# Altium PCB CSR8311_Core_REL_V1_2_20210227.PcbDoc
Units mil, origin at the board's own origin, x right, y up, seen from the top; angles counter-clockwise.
Board outline 1105 x 1105 mil, 2 copper layers (Top Layer, Bottom Layer), stack 50.044 mil thick; 31 components, 38 nets, 155 pads, 42 vias.
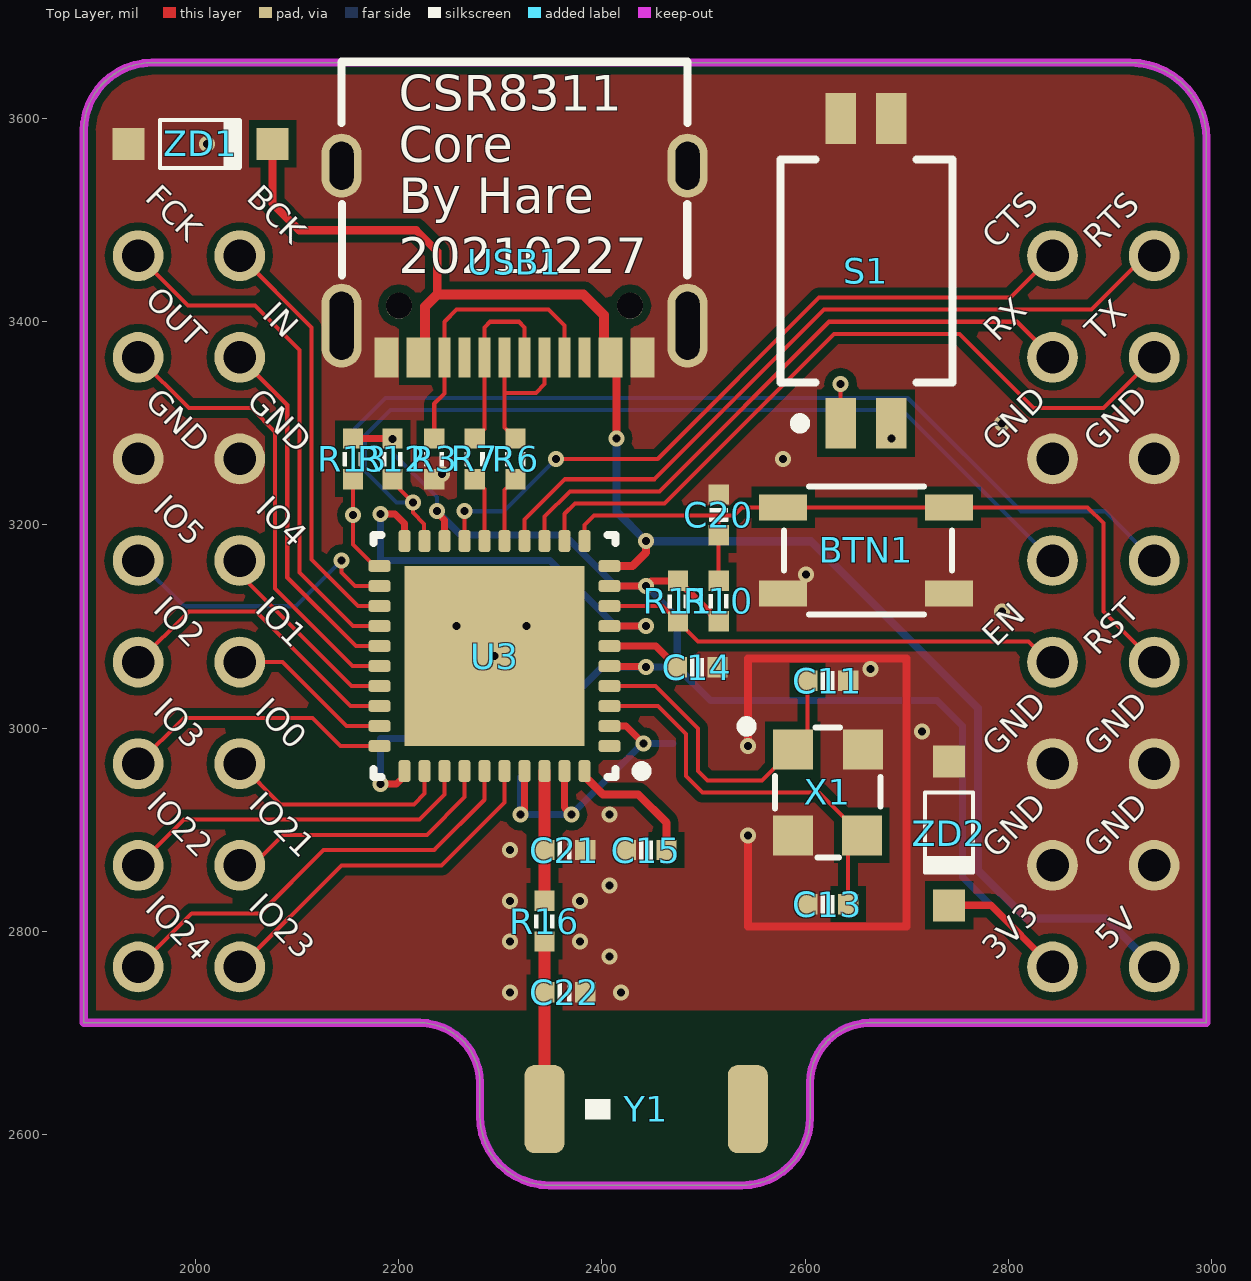
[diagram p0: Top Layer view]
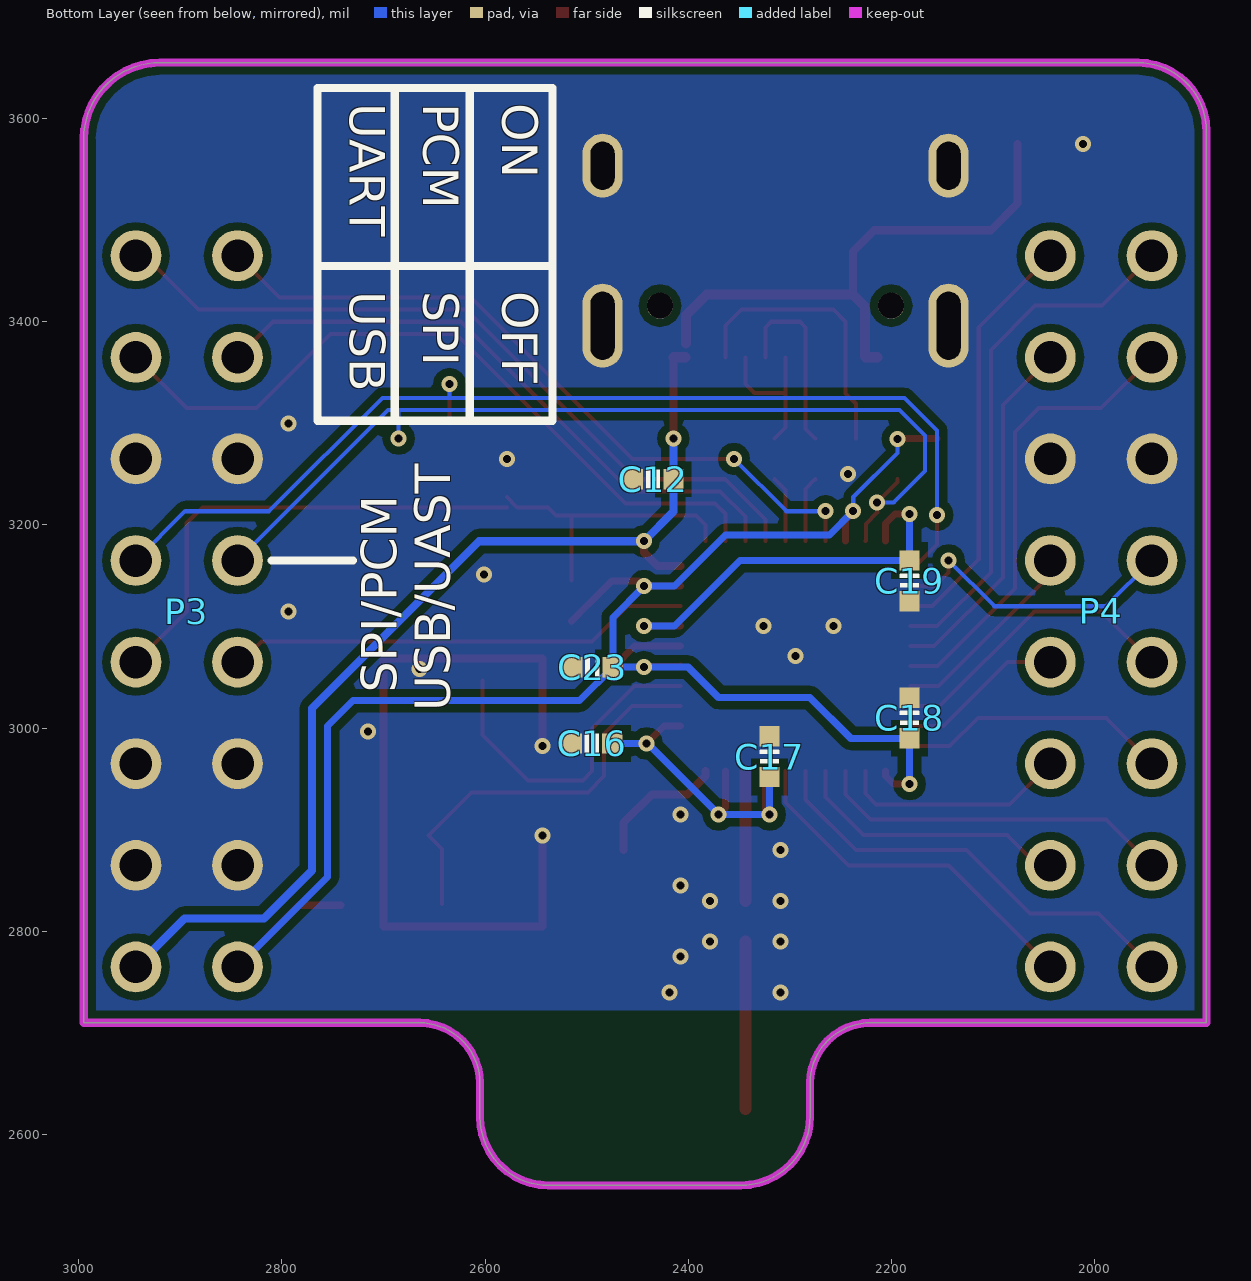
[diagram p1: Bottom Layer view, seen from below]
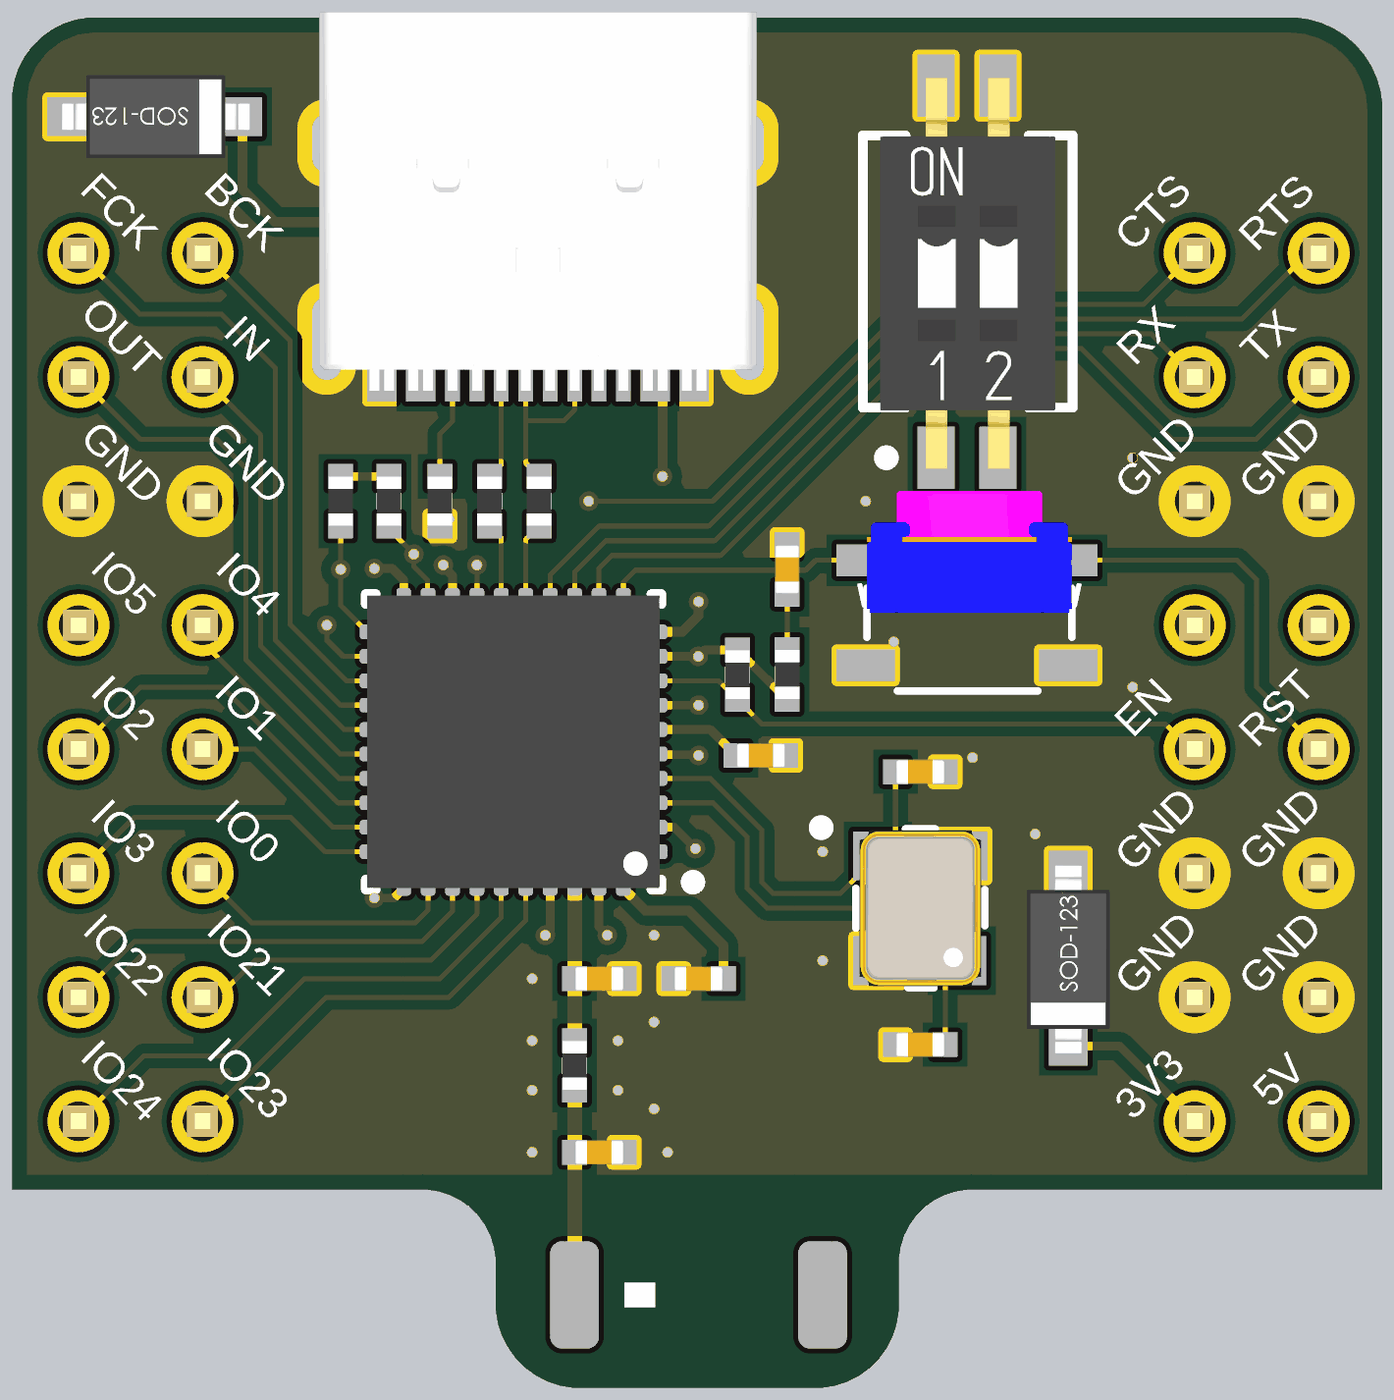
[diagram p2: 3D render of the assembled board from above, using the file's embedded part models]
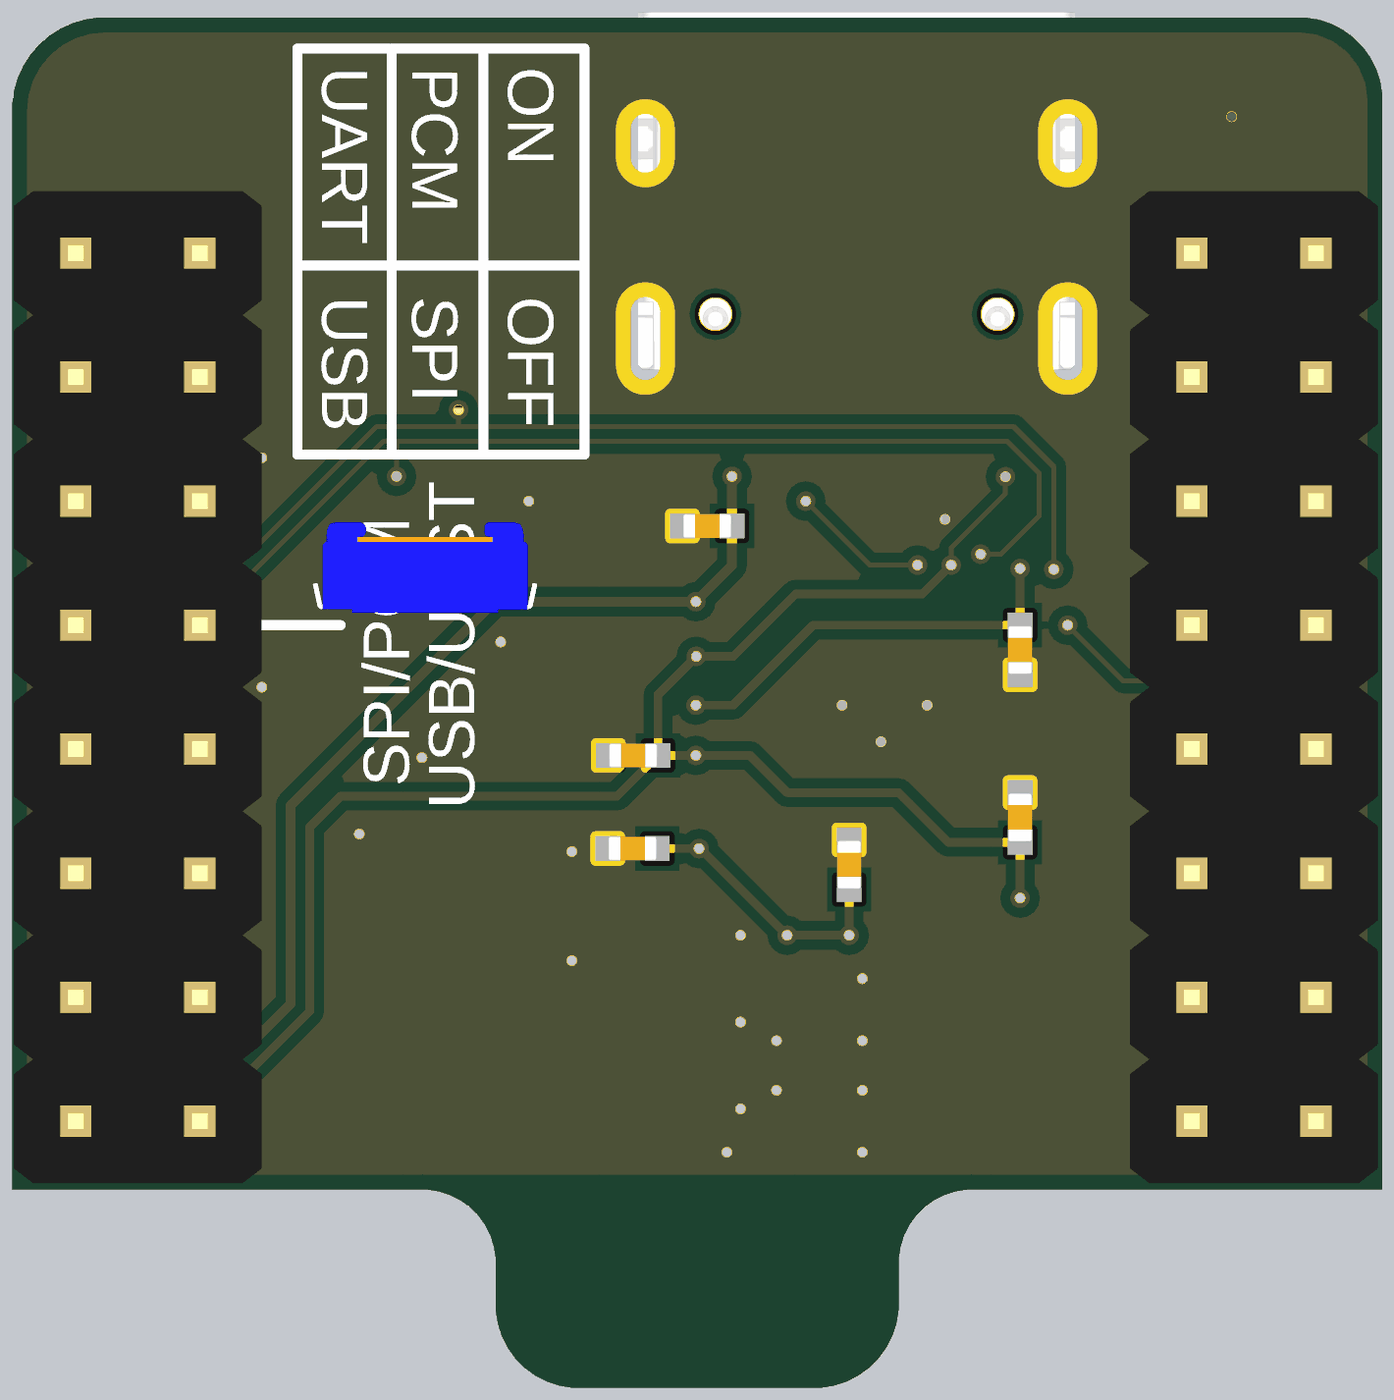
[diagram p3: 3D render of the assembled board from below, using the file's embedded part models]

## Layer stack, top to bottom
Top Solder: solder mask 0.4, Solder Resist, Dk 3.5
Top Layer: signal copper 1.4
Dielectric 1: dielectric 47.2441, FR-4, Dk 4.8
Bottom Layer: signal copper 1.4
Bottom Solder: solder mask 0.4, Solder Resist, Dk 3.5

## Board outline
2220.5,2710 cw(c2220.5,2650.51) 2280,2650.51 2280,2618.28 ccw(c2348.28,2618.28) 2348.28,2550 2537.61,2550 ccw(c2537.61,2617.39) 2605,2617.39 2605,2650.5 cw(c2664.5,2650.5) 2664.5,2710 2995,2710 2995,3580 ccw(c2920,3580) 2920,3655 1957.39,3655 ccw(c1957.39,3587.61) 1890,3587.61 1890,2710

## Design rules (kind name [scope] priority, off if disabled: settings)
Clearance [All] p1: gap=7.87 ignorepadtopadclearanceinfootprint=TRUE
ComponentClearance [All] p1: gap=0 collisioncheckmode=3 verticalgap=0 showdistances=FALSE
DiffPairsRouting [All] p1: maxlimit=10 minlimit=10 mostfreqgap=10 toplayer_minwidth=7.87 toplayer_maxwidth=15 toplayer_prefwidth=7.87 bottomlayer_minwidth=7.87 bottomlayer_maxwidth=15 bottomlayer_prefwidth=7.87 maxuncoupledlength=500
MatchedLengths SD_CARD_MatchedLengths [InNetClass('SD_CARD')] p1: tolerance=400 checknetsindiffpair=FALSE checkdiffpairvsdiffpair=TRUE checkxsignals=TRUE checkothers=TRUE
PolygonConnect PolygonConnect_wifi [HasFootprint('RTL8723DU_MOUDLE')] p1: connectstyle=Relief reliefconductorwidth=10 reliefentries=4 polygonreliefangle="90 Angle" airgapwidth=10
PolygonConnect PolygonConnect_Res [HasFootprint('RES_0603')] p2: connectstyle=Relief reliefconductorwidth=10 reliefentries=4 polygonreliefangle="90 Angle" airgapwidth=10
PolygonConnect PolygonConnect_Core [HasFootprint('CORE-82PIN-SMD')] p3: connectstyle=Relief reliefconductorwidth=10 reliefentries=4 polygonreliefangle="90 Angle" airgapwidth=10
PolygonConnect [All] p4: connectstyle=Direct reliefconductorwidth=10 reliefentries=4 polygonreliefangle="90 Angle" airgapwidth=10
RoutingVias [All] p1: holewidth=28 width=50 viastyle="Through Hole" minholewidth=7.87 minwidth=15.75 maxholewidth=28 maxwidth=50
SolderMaskExpansion [All] p1: expansion=4
Width Width_PWR [InNetClass('PWR')] p1: maxlimit=23.62 minlimit=7.87 preferedwidth=10
Width [All] p2: maxlimit=23.62 minlimit=4 preferedwidth=8
28 further rules are at their usual default settings.

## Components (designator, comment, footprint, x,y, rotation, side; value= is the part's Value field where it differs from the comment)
BTN1 "Button" BTN-4P-4.2*3.4*2.5 2660,3175 r180 top
C11 "10pF" CAP_0402 2622.41,3046.76 r180 top
C12 "2.2uF" CAP_0402 2434.45,3245 r0 bottom
C13 "10pF" CAP_0402 2622.41,2826.76 r0 top
C14 "2.2uF" CAP_0402 2493.85,3060 r180 top
C15 "470nF" CAP_0402 2443.59,2880 r180 top
C16 "15pF" CAP_0402 2494.69,2984.98 r0 bottom
C17 "2.2uF" CAP_0402 2320,2971.88 r90 bottom
C18 "0.1uF" CAP_0402 2182.17,3010 r270 bottom
C19 "2.2uF" CAP_0402 2182.17,3145 r270 bottom
C20 "0.1uF" CAP_0402 2515,3210 r90 top
C21 "NC" CAP_0402 2363.59,2880 r180 top locked
C22 "NC" CAP_0402 2363.59,2740 r180 top locked
C23 "2.2uF" CAP_0402 2494.17,3060 r0 bottom
P3 "DIP 2x8" HDR2X8_2.54_180 2943.59,3465 r180 bottom locked
P4 "DIP 2x8" HDR2X8_2.54_180 2043.59,3465 r180 bottom locked
R3 "5.1K" RES_0402 2235,3265 r90 top
R6 "22R" RES_0402 2315,3265 r90 top
R7 "22R" RES_0402 2275,3265 r90 top
R10 "10K" RES_0402 2515,3125.19 r90 top
R11 "10K" RES_0402 2475,3125 r270 top
R12 "10K" RES_0402 2193.98,3265 r270 top
R13 "10K" RES_0402 2155,3265 r270 top
R16 "0R" RES_0402 2343.59,2810 r270 top locked
S1 "SW-2P" SW-SMD-2-1.27 2660.59,3448.63 r90 top
U3 "CSR8311A08" QFN-40-P0.5 2295.37,3071.98 r90 top locked
USB1 "Type-C" USB-Type-C 2314.06,3459.29 r90 top locked
X1 "M26000J134" XTAL_3225-4 2622.41,2936.76 r270 top
Y1 "AN2051-245" ANT_2.4G_5.1X2.0 2443.59,2625 r0 top locked
ZD1 "BZT52C5V1S" SOD-123 2005,3575 r180 top
ZD2 "BZT52C3V9S" SOD-123 2741.69,2896.5 r90 top

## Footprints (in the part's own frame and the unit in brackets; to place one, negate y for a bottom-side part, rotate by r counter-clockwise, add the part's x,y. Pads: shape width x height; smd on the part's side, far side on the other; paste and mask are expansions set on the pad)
ANT_2.4G_5.1X2.0 [mm]
  rrect50% 1x2.2 smd: 1(-2.54,0) 2(2.54,0)
  silkscreen extent -1.52,-0.25 -0.89,0.25
BTN-4P-4.2*3.4*2.5 [mm] "SKRPABE010"
  rect 1.2x0.65 smd: 1(-2.075,1.075) 1(2.075,1.075) 2(-2.075,-1.075) 2(2.075,-1.075)
  silkscreen extent -2.15,-1.6 2.05,1.6, body extent -2.35,-1.6 2.25,1.6, height 2.5
CAP_0402 [mil]
  rect 20x20 smd: 1(-20,0) 2(20,0)
  silkscreen extent -7,-9 7,9, body extent -20,-10 20,10, height 20
HDR2X8_2.54_180 [mil]
  round 50 hole 32: 1(0,0) 2(100,0) 3(0,-100) 4(100,-100) 5(0,-200) 6(100,-200) 7(0,-300) 8(100,-300) 9(0,-400) 10(100,-400) 11(0,-500) 12(100,-500) 13(0,-600) 14(100,-600) 15(0,-700) 16(100,-700)
  body extent -50,-750 150,50, height 335
QFN-40-P0.5 [mm] "PQFN, 40-Leads, Body 5.98x5.98mm, Pitch 0.50mm, Thermal Pad 4.62x4.62mm, IPC Medium Density"
  rrect50% 0.3x0.55 smd: 1(-2.275,-2.851) 2(-1.775,-2.851) 3(-1.275,-2.851) 4(-0.775,-2.851) 5(-0.275,-2.851) 6(0.225,-2.851) 7(0.725,-2.851) 8(1.225,-2.851) 9(1.725,-2.851) 10(2.225,-2.851) 21(2.225,2.902) 22(1.725,2.902) 23(1.225,2.902) 24(0.725,2.902) 25(0.225,2.902) 26(-0.275,2.902) 27(-0.775,2.902) 28(-1.275,2.902) 29(-1.775,2.902) 30(-2.275,2.902)
  rrect50% 0.55x0.3 smd: 11(2.851,-2.225) 12(2.851,-1.725) 13(2.851,-1.225) 14(2.851,-0.725) 15(2.851,-0.225) 16(2.851,0.275) 17(2.851,0.775) 18(2.851,1.275) 19(2.851,1.775) 20(2.851,2.275) 31(-2.902,2.275) 32(-2.902,1.775) 33(-2.902,1.275) 34(-2.902,0.775) 35(-2.902,0.275) 36(-2.902,-0.225) 37(-2.902,-0.725) 38(-2.902,-1.225) 39(-2.902,-1.725) 40(-2.902,-2.225)
  rect 4.5x4.5 smd: 41(-0.025,0.025)
  silkscreen extent -3.05,-3.77 3,3.05, body extent -3.03,-2.97 2.97,3.03, height 0.9
RES_0402 [mil]
  rect 20x20 smd: 1(-20,0) 2(20,0)
  silkscreen extent -7,-10 7,10, body extent -20,-10 20,10, height 14
SOD-123 [mm]
  rect 0.8x0.8 smd: 1(1.8,0) 2(-1.8,0)
  silkscreen extent -1.02,-0.6 1.02,0.6, body extent -1.95,-0.85 1.9,0.85, height 1.42
SW-SMD-2-1.27 [mm]
  rect 1.27x0.76 smd: 1(-3.775,0.65) 2(-3.775,-0.62) 3(3.845,-0.62) 4(3.845,0.65)
  silkscreen extent -3.9,-2.15 2.82,2.15, body extent -4,-1.79 4,1.79, height 2.1
USB-Type-C [mm]
  round 0.65 hole 0.65: 0(-1.105,2.89) 0(-1.105,-2.89)
  oval 1.6x1 hole 0.6 slot 1.2 at 0 deg: 1(2.395,4.325) 2(2.395,-4.325)
  oval 2.1x1 hole 0.6 slot 1.7 at 0 deg: 3(-1.605,-4.325) 4(-1.605,4.325)
  rect 1x0.3 smd: A1(-2.395,-3.35) A4(-2.395,-2.55) A5(-2.395,-1.25) A6(-2.395,-0.25) A7(-2.395,0.25) A8(-2.395,1.25) A9(-2.395,2.55) A12(-2.395,3.35) B1(-2.395,3.05) B4(-2.395,2.25) B5(-2.395,1.75) B6(-2.395,0.75) B7(-2.395,-0.75) B8(-2.395,-1.75) B9(-2.395,-2.25) B12(-2.395,-3.05)
  silkscreen extent -0.34,-4.33 4.99,4.33, body extent -2.67,-4.48 5.08,4.48, height 3.26
XTAL_3225-4 [mm]
  rect 1x1 smd: 1(-1.074,-0.874) 2(1.074,-0.874) 3(1.074,0.848) 4(-1.074,0.874)
  silkscreen extent -1.78,-2.16 1.63,1.32, body extent -1.6,-1.25 1.6,1.25, height 0.61

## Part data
C11 C12 C13 C14 C15 C16 C17 C18 C19 C20 C21 C22 C23: library part CAP, "Capacitor"
P3 P4: library part HDR2x8, "Header"
R3 R6 R7 R10 R11 R12 R13 R16: library part RES, "Resistor"
S1: "拨码开关2P"
U3: library part CSR8311, "Bluetooth v4.1 single-chip radio and baseband IC for automotive applications."
USB1: library part USB-Type-C
X1: library part XTAL-4P
Y1: library part ANTENNA
ZD1 ZD2: library part Diode-ZD, "Zender Diode"

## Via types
v1: diameter 15.75, hole 7.87, Top Layer to Bottom Layer, tented both sides, 42 vias

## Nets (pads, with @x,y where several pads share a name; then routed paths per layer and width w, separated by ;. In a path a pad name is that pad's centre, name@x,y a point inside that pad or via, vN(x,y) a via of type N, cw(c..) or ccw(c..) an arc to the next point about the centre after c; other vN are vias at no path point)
BT_NRST: BTN1.2 C20.1 P3.9 R10.2 U3.11 | length 765.8
  Top Layer w4: U3.11 2382.96,3199.91 2392.42,3209.38 2515,3209.38 ; R10.2 2515,3209.38 ; BTN1.2@2578.31,3217.32 2741.69,3217.32 2878.06,3217.32 2893.59,3201.79 2893.59,3115 P3.9 ; BTN1.2@2578.31,3227.32 2568.31,3217.32 2537.98,3217.32 2530.04,3209.38 2515,3209.38
BT_PCM2_CLK: P4.1 U3.23 | length 414.3
  Top Layer w4: P4.1 2114.08,3394.5 2114.08,3165.92 2159.81,3120.19 U3.23
BT_PCM2_IN: P4.3 U3.25 | length 354.8
  Top Layer w4: P4.3 2090.33,3318.25 2090.33,3148.38 2157.89,3080.82 U3.25
BT_PCM2_OUT: P4.4 U3.26 | length 453.7
  Top Layer w4: P4.4 1993.59,3315 2055,3315 2078.46,3291.54 2078.46,3137.33 2154.65,3061.13 U3.26
BT_PCM2_SYNC: P4.2 U3.24 | length 516.8
  Top Layer w4: P4.2 1992.8,3415.79 2058.77,3415.79 2102.21,3372.35 2102.21,3153.3 2155,3100.5 U3.24
BT_PIO0: P4.11 U3.32 | length 225
  Top Layer w4: P4.11 2083.59,2925 2215,2925 2225.48,2935.48 U3.32
BT_PIO1: P4.9 U3.29 | length 163.6
  Top Layer w4: P4.9 2085.85,3065 2148.77,3002.08 U3.29
BT_PIO2: P4.10 U3.28 | length 296.9
  Top Layer w4: P4.10 1993.59,3115 2059.4,3115 2152.64,3021.76 U3.28
BT_PIO3: P4.12 U3.30 | length 267.6
  Top Layer w4: P4.12 1988.59,3010 2115,3010 2142.61,2982.39 U3.30
BT_PIO4: P4.7 U3.27 | length 196.7
  Top Layer w4: P4.7 2045.08,3163.5 2045.08,3149.92 2153.55,3041.45 U3.27
BT_PIO5: P4.8 U3.22 | length 292.2
  Top Layer w4: v1(2143.78,3165) 2143.78,3153.01 2156.92,3139.87 U3.22
  Bottom Layer w4: P4.8 1988.59,3120 2098.78,3120 v1(2143.78,3165)
BT_PIO21: P4.13 U3.34 | length 274.7
  Top Layer w4: P4.13 2056.03,2865 2086.03,2895 2227.72,2895 2264.85,2932.12 U3.34
BT_PIO22: P4.14 U3.33 | length 353.5
  Top Layer w4: P4.14 1988.59,2910 2220.46,2910 2245.16,2934.7 U3.33
BT_PIO23: P4.15 U3.36 | length 358.5
  Top Layer w4: P4.15 2143.59,2865 2242.27,2865 2304.22,2926.95 U3.36
BT_PIO24: P4.16 U3.35 | length 437.3
  Top Layer w4: P4.16 1996.31,2817.72 2063.76,2817.72 2126.03,2880 2235,2880 2284.53,2929.53 U3.35
BT_RF: C21.2 R16.1 U3.38 | length 127.7
  Top Layer w11.81: R16.1 C21.2 U3.38
BT_SPI_PCM: P3.7 R13.2 S1.1 U3.21 | length 1102.3
  Top Layer w4: R13.2 v1(2155,3210) 2155,3180.76 2176.2,3159.56 U3.21 ; S1.1 v1(2635,3338.59)
  Bottom Layer w4: v1(2155,3210) 2155,3292.75 2187.25,3325 2635,3325 ; v1(2635,3338.59) 2635,3325 ; P3.7 2895.08,3213.5 2812.56,3213.5 2701.06,3325 2635,3325
BT_UART_CTS: P3.2 U3.17 | length 712.2
  Top Layer w4: U3.17 v1(2264.85,3213.5) ; v1(2355,3265) 2455,3265 2613.75,3423.75 2802.33,3423.75 P3.2
  Bottom Layer w4: v1(2264.85,3213.5) 2303.5,3213.5 v1(2355,3265)
BT_UART_RTS: P3.1 U3.14 | length 748.3
  Top Layer w4: U3.14 2323.9,3205.23 2363.67,3245 2451.79,3245 2618.67,3411.87 2881.87,3411.87 2935,3465 P3.1
BT_UART_RX: P3.4 U3.13 | length 617.9
  Top Layer w4: U3.13 2343.59,3208.13 2368.59,3233.13 2456.71,3233.13 2623.58,3400 2808.59,3400 P3.4
BT_UART_TX: P3.3 U3.12 | length 731.5
  Top Layer w4: U3.12 2363.27,3211.02 2373.5,3221.25 2461.63,3221.25 2628.5,3388.13 2751.87,3388.13 2825,3315 2893.59,3315 P3.3
BT_USB_D_N: R6.1 U3.15 | length 65.2
  Top Layer w4: U3.15 2304.22,3234.22 R6.1
BT_USB_D_P: R7.1 U3.16 | length 64.7
  Top Layer w4: R7.1 2284.53,3235.47 U3.16
BT_USB_UART: P3.8 R12.2 S1.2 U3.19 | length 945.1
  Top Layer w4: R12.2 2193.98,3242.32 v1(2213.98,3222.27) v1(2213.98,3222.27) 2213.98,3212.15 2225.07,3201.06 2225.07,3184.63 U3.19
  Bottom Layer w4: v1(2213.98,3222.27) 2197.73,3222.27 2166.87,3253.13 2166.87,3287.83 2192.17,3313.13 2685,3313.13 ; v1(2685,3285) 2685,3313.13 ; P3.8 2695.46,3313.13 2685,3313.13
BT_VREG_EN: P3.10 R11.2 U3.8 | length 458.8
  Top Layer w4: U3.8 2459.81,3120.19 R11.2 2494.69,3085.31 2820.06,3085.31 2840.38,3065 P3.10
GND: BTN1.1 C11.1 C12.2 C13.1 C14.1 C15.2 C16.2 C17.2 C18.1 C19.2 C20.2 C21.1 C22.1 C23.2 P3.5 P3.6 P3.11 P3.12 P3.13 P3.14 P4.5 P4.6 R3.1 S1.3 S1.4 U3.41 USB1.1 USB1.2 USB1.3 USB1.4 USB1.A1 USB1.A12 USB1.B1 USB1.B12 X1.2 X1.4 ZD1.1 ZD2.1 | length 752.2
  Top Layer w7.87: v1(2543.59,2894.49) 2543.59,2804.95 2700,2804.95 2700,3068.57 2543.59,3068.57 v1(2543.59,2982.39)
  other v1: 2309.37,2740 2418.59,2740 2407.63,2775 2309.37,2790 2378.59,2790 2309.37,2830 2378.59,2830 2407.63,2845 2309.37,2880 2407.63,2915 2715,2996.64 2664.5,3058.18 2294.37,3070.98 2257.13,3100.5 2325.71,3100.5 2793.59,3115 2601,3151.47 2242.75,3250.31 2578.31,3265 2793.59,3300 2011.56,3575
NetC14_2: C14.2 U3.6 | length 74.9
  Top Layer w7: U3.6 2453.03,3080.82 C14.2
NetC15_1: C15.1 U3.40 | length 131.5
  Top Layer w8: U3.40 2382.96,2952.8 2401.01,2934.75 2435.79,2934.75 2463.59,2906.95 C15.1
NetC16_1: C16.1 C17.1 U3.2 U3.37 U3.39 | length 346.3
  Top Layer w7: v1(2320,2915) 2323.9,2918.9 U3.37 ; U3.39 2363.27,2921.73 v1(2370,2915) ; U3.2 2423.9,3002.08 v1(2441.06,2984.89)
  Bottom Layer w7: C17.1 v1(2320,2915) v1(2370,2915) 2439.91,2984.91 v1(2441.06,2984.89) 2441.15,2984.98 C16.1@2469.98,2984.98
NetC19_1: C19.1 U3.7 U3.20 | length 414.4
  Top Layer w7: v1(2182.17,3210.68) 2196.54,3210.68 2205.79,3201.42 U3.20 ; U3.7 v1(2443.59,3100.5)
  Bottom Layer w7: v1(2182.17,3210.68) C19.1 2348.97,3165 2413.47,3100.5 v1(2443.59,3100.5)
NetC22_2: C22.2 R16.2 Y1.1 | length 165
  Top Layer w11.81: Y1.1 C22.2 R16.2
NetR3_2: R3.2 USB1.A5 USB1.B5 | length 279.9
  Top Layer w4: R3.2 2235,3319.29 2245.16,3329.45 USB1.B5 2245.16,3400 2257.03,3411.87 2347.5,3411.87 2363.27,3396.1 USB1.A5
USB_D_N: R6.2 USB1.A7 USB1.B7 | length 154
  Top Layer w4: USB1.A7 2304.22,3330.39 ; R6.2 2304.22,3295.78 2304.22,3330.39 ; USB1.B7 2343.59,3338.59 2335,3330 2304.61,3330 2304.22,3330.39
USB_D_P: R7.2 USB1.A6 USB1.B6 | length 186.9
  Top Layer w4: R7.2 2284.53,3294.53 USB1.B6 2284.53,3394.53 2290,3400 2318.43,3400 2323.9,3394.53 USB1.A6
VCC_3V3: C18.2 C23.1 P3.16 R10.1 R11.1 R12.1 R13.1 U3.5 U3.9 U3.18 U3.31 ZD2.2 | length 1756.5
  Top Layer w7: R13.1 R12.1 ; v1(2182.17,2945) 2197.99,2945 2205.79,2952.8 U3.31 ; v1(2237.72,3213.5) 2237.72,3212.37 2245.16,3204.93 U3.18 ; U3.5 2408.19,3060.57 2443.02,3060.57 v1(2443.59,3060) ; U3.9 v1(2443.31,3139.87) 2448.44,3145 R11.1 2498.41,3121.59 2498.6,3121.59 R10.1 ; ZD2.2 2782.95,2825.63 P3.16
  Bottom Layer w4: v1(2193.98,3284.69) 2194.14,3284.53 2194.14,3270.81 2237.57,3227.38 2237.57,3216.7 v1@2236.05,3215.18
  Bottom Layer w7: v1(2182.17,2945) C18.2 2240,2990 2280,3030 2370,3030 2400,3060 v1(2443.59,3060) C23.1 ; v1@2236.05,3215.18 v1(2237.72,3213.5) 2237.72,3213.4 2261.06,3190.07 2363.27,3190.07 2413.47,3139.87 v1(2443.31,3139.87) 2474.17,3109.02 C23.1 ; P3.16 2755,2853.59 2755,3002.15 2730.01,3027.13 2507.04,3027.13 C23.1
VCC_5V: C12.1 P3.15 U3.10 USB1.A4 USB1.A9 USB1.B4 USB1.B9 ZD1.2 | length 1586.3
  Top Layer w8: ZD1.2 2075.87,3516.34 2102.21,3490 2217.27,3490 2238,3469.27 2238,3426.75 ; U3.10 2430.24,3159.56 2443.59,3172.9 v1(2443.59,3183.98) ; v1(2414.45,3285) USB1.A4
  Top Layer w10: USB1.A9 USB1.B4 2225.95,3365.47 2225.95,3414.7 2238,3426.75 2381.84,3426.75 2402.17,3406.42 USB1.B9@2402.17,3378.78 ; USB1.B9 USB1.A4
  Bottom Layer w8: v1(2414.45,3285) C12.1 2414.45,3213.12 v1(2443.59,3183.98) 2606.02,3183.98 2770.37,3019.63 2770.37,2859.95 2817.66,2812.66 2895.92,2812.66 P3.15
XTAL26_IN: C11.2 U3.4 X1.1 | length 329.7
  Top Layer w4: U3.4 2452.89,3041.45 2494.69,2999.65 2494.69,2957.72 2503.77,2948.64 2557.61,2948.64 X1.1 2602.41,2993.44 C11.2
XTAL26_OUT: C13.2 U3.3 X1.3 | length 398.5
  Top Layer w4: U3.3 2455.31,3021.76 2482.81,2994.27 2482.81,2952.81 2498.85,2936.76 2613.54,2936.76 X1.3 2642.41,2881.09 C13.2
pads on no net: U3.1 USB1.0 USB1.A8 USB1.B8 Y1.2

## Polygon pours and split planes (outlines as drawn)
GND on Top Layer "NONET_L-01_P-001" (solid, remove dead copper, pour order 8): 1890,3675 2995,3675 2995,2720 1890,2720
no net on Top Layer "NONET_L01_P000" (solid, remove dead copper, pour order 0): -1090.59,-350.01
GND on Bottom Layer "NONET_L-01_P-001" (solid, remove dead copper, pour order 10): 1890,2720 2995,2720 2995,3685 1890,3685

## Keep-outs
Keep-Out Layer:
  the board outline again, w8

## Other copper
Top Layer:
  pour cut-out: 2192.17,3180 2196.73,3175.44 2403.6,3175.44 2403.6,2970.51 2389.08,2955.99 2193.77,2955.99
  pour cut-out: 2195,2720 2197.13,2722.13 2678.86,2722.13 2678.86,2534.52 2683.37,2530 2668.37,2515 2192.21,2515
Bottom Layer:
  pour cut-out: 2195.75,2722.13 2677.79,2722.13 2677.79,2522.5 2255.04,2522.5

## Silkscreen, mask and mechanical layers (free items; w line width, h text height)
Top Overlay:
  text "CSR8311" at 2199.98,3595.77 h60
  text "Core" at 2199.98,3545 h60
  text "FCK" at 1943.59,3515 h39.37 r315
  text "BCK" at 2043.39,3515 h39.37 r315
  text "By Hare" at 2199.98,3495 h60
  text "CTS" at 2793.58,3465 h39.37 r45
  text "RTS" at 2893.58,3465 h39.37 r45
  text "20210227" at 2199.98,3435.77 h60
  text "OUT" at 1943.59,3415 h39.37 r315
  text "IN" at 2058.77,3400 h39.37 r315
  text "RX" at 2795.19,3373.24 h39.37 r45
  text "TX" at 2895.19,3373.24 h39.37 r45
  text "GND" at 1943.59,3315 h39.37 r315
  text "GND" at 2043.59,3315 h39.37 r315
  text "GND" at 2793.58,3265 h39.37 r45
  text "GND" at 2893.58,3265 h39.37 r45
  text "IO5" at 1951.79,3210 h39.37 r315
  text "IO4" at 2052.54,3209.25 h39.37 r315
  text "IO2" at 1951.79,3110 h39.37 r315
  text "IO1" at 2051.79,3110 h39.37 r315
  text "EN" at 2793.59,3073.24 h39.37 r45
  text "RST" at 2893.58,3065 h39.37 r45
  text "IO3" at 1951.79,3010 h39.37 r315
  text "IO0" at 2051.79,3010 h39.37 r315
  text "GND" at 2793.58,2965 h39.37 r45
  text "GND" at 2893.58,2965 h39.37 r45
  text "IO22" at 1945.35,2917.72 h39.37 r315
  text "IO21" at 2045.35,2917.72 h39.37 r315
  text "GND" at 2793.58,2865 h39.37 r45
  text "GND" at 2893.58,2865 h39.37 r45
  text "IO23" at 2045.35,2817.72 h39.37 r315
  text "IO24" at 1943.59,2816 h39.37 r315
  text "5V" at 2905,2775 h39.37 r45
  text "3V3" at 2793.59,2765 h39.37 r45
Bottom Overlay:
  lines w8: 2535,3455 2765,3455 ; 2615,3302.59 2615,3630 ; 2688.91,3302.59 2688.91,3630 ; 2730,3165 2810,3165 ; 2533.41,3302.59 2765,3302.59 2765,3630 2533.41,3630 2533.41,3302.59
  text "ON" at 2595,3615 h60 r90
  text "PCM" at 2672.41,3615 h60 r90
  text "UART" at 2745,3615 h60 r90
  text "OFF" at 2595,3430 h60 r90
  text "SPI" at 2672.41,3430 h60 r90
  text "USB" at 2745,3430 h60 r90
  text "SPI/PCM" at 2675,3035 h60 r270
  text "USB/UAST" at 2622.41,3016.76 h60 r270
Mechanical 1:
  the board outline again, w8
Top Component:
  lines w8: 2043.59,3165 2443.59,3165 ; 2443.59,4481.41 2443.59,3165 ; 2450.66,2305 2443.59,2312.07 2443.59,3165 ; 2843.59,3165 2443.59,3165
